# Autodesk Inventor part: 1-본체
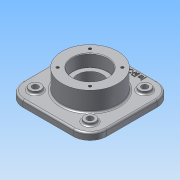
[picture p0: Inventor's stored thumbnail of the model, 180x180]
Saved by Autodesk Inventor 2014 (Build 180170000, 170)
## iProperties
Created: 2015-09
Part Number: 1-본체
Material: 알루미늄 6061
Document SubType Name: Modeling
Designer: study
Density: 2.71 g/cm^3
Appearance: 알루미늄 - 평지
Mass: 1464.68 g
Surface Area: 800.934 cm^2
Volume: 540.471 cm^3
Author: study
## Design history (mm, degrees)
sketch "스케치1"
  geometry: L1 (-75, -75)-(75, -75); L2 (75, -75)-(75, 75); L3 (75, 75)-(-75, 75); L4 (-75, 75)-(-75, -75); L5 (-75, -75)-(75, 75); L6 (75, -75)-(-75, 75); 1 further point
  constraints: 12 end point, 2 midpoint, 2 parallel, 1 horizontal, 1 perpendicular
  dimensions: "d0" = 150 distance of L2.end L3.end; "d1" = 150 distance of L1.end L2.end
extrude "돌출1" new body sketch "스케치1" distance "d2" = 12; taper "d3" = 0 deg
fillet "모깎기1" dims "d4" = 30
node "작업 평면1"
sketch "스케치2"
  geometry: C1 r 50 at (0, 0); 1 further point
  constraints: 1 centre point, 1 coincident
  dimensions: "d6" = 100 diameter of C1
extrude "돌출2" join sketch "스케치2" distance "d7" = 70; taper "d8" = 0 deg
sketch "스케치7"
  geometry: L1 (-49, -49)-(49, -49); L2 (49, -49)-(49, 49); L3 (49, 49)-(-49, 49); L4 (-49, 49)-(-49, -49); L5 (-49, -49)-(49, 49); L6 (49, -49)-(-49, 49); C1 r 50 at (0, 0) reference; C2 r 10 at (-49, 49); C3 r 10 at (49, 49); C4 r 10 at (-49, -49); C5 r 10 at (49, -49)
  constraints: 12 end point, 4 centre point, 4 coincident, 3 equal radius, 2 midpoint, 2 parallel, 1 horizontal, 1 perpendicular
  dimensions: "d58" = 98 distance of L2.end L3.end; "d59" = 98 distance of L1.end L2.end; "d60" = 20 diameter of C2
extrude "돌출4" join sketch "스케치7" distance "d61" = 5; taper "d62" = 0 deg
sketch "스케치4"
  geometry: C1 r 50 at (0, 0) reference; C2 r 50 at (0, 0) reference; 1 further point
  constraints: 1 vertical alignment, 1 other
  dimensions: "d12" = 65 distance of C1.centre point (0, 65)
feature "엠보싱1" sketch "스케치4" dims "d0" = 150, "d1" = 150, "d13" = 1, "d14" = 0
sketch "스케치8"
  geometry: C1 r 10 at (0, 0) reference; C2 r 10 at (0, -98) reference; C3 r 10 at (98, -98) reference; C4 r 10 at (98, 0) reference; 5 further points
  constraints: 4 coincident
hole "구멍5" sketch "스케치8" at (0, 0), (0, -98), (98, -98), (98, 0) diameter "d63" = 11; stored, may be unused: countersink angle "d67" = 90 deg, drill point angle "d69" = 0 deg; dims "d64" = 10, "d65" = 62, "d66" = 22, "d68" = 17
hole "구멍2" diameter "d24" = 45; stored, may be unused: countersink angle "d28" = 90 deg, drill point angle "d30" = 0 deg; dims "d22" = 10, "d23" = 10, "d25" = 6, "d26" = 62, "d27" = 22, "d29" = 48
hole "구멍3" diameter "d33" = 45; stored, may be unused: countersink angle "d37" = 90 deg, drill point angle "d39" = 0 deg; dims "d31" = 10, "d32" = 10, "d34" = 6, "d35" = 62, "d36" = 22, "d38" = 48
sketch "스케치6"
  geometry: L1 (0, 0)-(41, 0); C1 r 31 at (0, 0) reference; C2 r 50 at (0, 0) reference; A1 r 41 centre (0, 0) between (-28.991, 28.991) and (28.991, 28.991); 2 further points
  constraints: 5 point on circle, 2 end point, 2 horizontal alignment, 1 centre point, 1 coincident, 1 horizontal, 1 vertical alignment
  dimensions: "d40" = 82 diameter of A1; "d41" = 45 deg dimension on C1.centre L1.end A1.end
hole "구멍4" sketch "스케치6" at (-28.991, 28.991), (28.991, 28.991), (-28.991, -28.991), (28.991, -28.991) diameter "d42" = 4.917; stored, may be unused: countersink angle "d46" = 90 deg, drill point angle "d48" = 118 deg; dims "d43" = 10, "d44" = 62, "d45" = 22, "d47" = 13
node "작업 평면2"
chamfer "모따기1" distance "d50" = 1; stored, may be unused: second distance "d51" = 2, angle "d52" = 45 deg
fillet "모깎기2" dims "d53" = 0.3
fillet "모깎기4" dims "d70" = 3
node "솔리드1"
mirror "대칭1"
node "투영된 루프3"
node "투영된 루프4"
node "투영된 루프5"
other parameters: "d5" = -23, "d49" = 12
